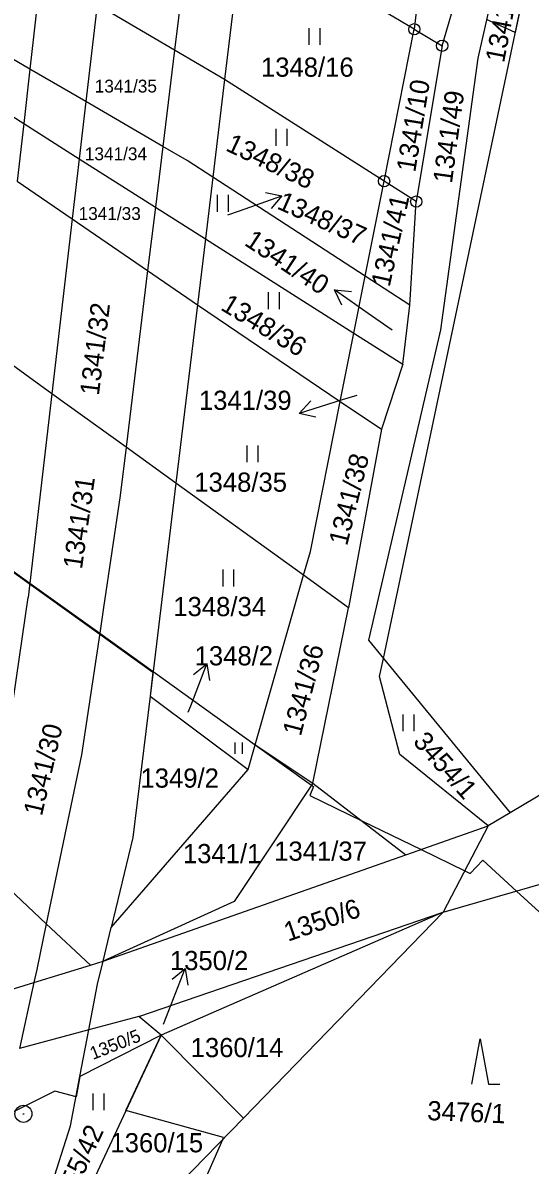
# Model space of a CAD drawing. Extents: x -735036 to -734743, y -1144813 to -1144181.
# Drawn here: x -734846.3 to -734801.3, y -1144707.5 to -1144606.3 of the extents above; entities that cross this region are included whole.
import ezdxf

# ---------------------------------------------------------------- set-up
doc = ezdxf.new("R2010")
doc.units = 0
for name, color, linetype in [('BPEJ', 7, 'Continuous'), ('Katastr_HRANICE DRÁHY', 7, 'Continuous'), ('Katastr_Hranice parcel', 7, 'Continuous'), ('Katastr_Parcelní čísla', 7, 'Continuous'), ('Katastr_Slučkované čáry', 7, 'Continuous'), ('Katastr_Značky kultur', 7, 'Continuous')]:
    doc.layers.add(name, color=color, linetype=linetype)

msp = doc.modelspace()

# ---------------------------------------------------------------- linework, layer by layer
at = {"layer": 'BPEJ'}
for points in [[(-734799.83, -1144593.94), (-734802.63, -1144607.21), (-734805.16, -1144606.06)], [(-734886.95, -1144596.85), (-734888.29, -1144609.47), (-734890, -1144625.5), (-734887.82, -1144626.59), (-734885, -1144628), (-734852.91, -1144650.88), (-734852.15, -1144651.42), (-734850.43, -1144652.65), (-734834.73, -1144663.85), (-734834.99, -1144666), (-734826.29, -1144672.48), (-734825.67, -1144670.31), (-734820.68, -1144673.87), (-734820.5, -1144674), (-734820.82, -1144674.78), (-734818.52, -1144675.9), (-734816.23, -1144677.02), (-734810.97, -1144679.57), (-734807.09, -1144681.45), (-734806.63, -1144681.68), (-734805.5, -1144680.5), (-734802.5, -1144683.25), (-734799.5, -1144686)], [(-734875.41, -1144811.46), (-734872.9, -1144805.78), (-734867.89, -1144794.43), (-734854.34, -1144763.72), (-734850.2, -1144754.32), (-734842.33, -1144736.48), (-734836.55, -1144723.38), (-734836.47, -1144723.21), (-734828.55, -1144705.26), (-734828.47, -1144705.07), (-734837.14, -1144702.69), (-734834.01, -1144696), (-734841.2, -1144699.67), (-734841.55, -1144701.48), (-734843.42, -1144700.96), (-734850.5, -1144704.5), (-734856.16, -1144706.13), (-734861.05, -1144707.56), (-734878.02, -1144712.44), (-734888.06, -1144715.34), (-734896.33, -1144716.95), (-734914.06, -1144720.39), (-734915.89, -1144720.74)]]:
    msp.add_lwpolyline(points, dxfattribs=at)
at = {"layer": 'Katastr_HRANICE DRÁHY'}
for points in [[(-734844.66, -1144601.82), (-734845.64, -1144610.44)], [(-734845.64, -1144610.44), (-734846.19, -1144615.27)], [(-734828.38, -1144611.37), (-734829.43, -1144620.02)], [(-734814.25, -1144620.37), (-734828.38, -1144611.37)], [(-734846.19, -1144615.27), (-734846.77, -1144620.37)], [(-734829.43, -1144620.02), (-734830.09, -1144625.49)], [(-734815.92, -1144628.78), (-734814.25, -1144620.37)], [(-734830.09, -1144625.49), (-734830.79, -1144631.32)], [(-734816.93, -1144633.84), (-734815.92, -1144628.78)], [(-734830.79, -1144631.32), (-734832.7, -1144647.12)], [(-734818.13, -1144639.88), (-734816.93, -1144633.84)], [(-734818.13, -1144639.88), (-734814.48, -1144642.35)], [(-734814.48, -1144642.35), (-734817.41, -1144658.17)], [(-734832.7, -1144647.12), (-734834.72, -1144663.79)], [(-734825.66, -1144670.29), (-734821.38, -1144655.27)], [(-734817.41, -1144658.17), (-734821.38, -1144655.27)], [(-734834.72, -1144663.79), (-734834.99, -1144666)], [(-734834.99, -1144666), (-734826.29, -1144672.48)], [(-734826.29, -1144672.48), (-734825.66, -1144670.29)]]:
    msp.add_lwpolyline(points, dxfattribs=at)
at = {"layer": 'Katastr_Hranice parcel'}
for points in [[(-734798.65, -1144577.31), (-734805.94, -1144609.48)], [(-734814.3, -1144662.64), (-734799.83, -1144593.94)], [(-734826.76, -1144597.94), (-734828.38, -1144611.37)], [(-734811.57, -1144606.92), (-734826.76, -1144597.94)], [(-734809.1, -1144608.38), (-734806.45, -1144599.27)], [(-734811.14, -1144603.11), (-734811.57, -1144606.92)], [(-734832.82, -1144608.77), (-734839.69, -1144604.74)], [(-734814.25, -1144620.37), (-734811.57, -1144606.92)], [(-734811.57, -1144606.92), (-734809.1, -1144608.38)], [(-734828.38, -1144611.37), (-734832.82, -1144608.77)], [(-734809.1, -1144608.38), (-734811.4, -1144622.18)], [(-734845.64, -1144610.44), (-734847.79, -1144609.19)], [(-734805.94, -1144609.48), (-734809.25, -1144633.53)], [(-734840.68, -1144613.32), (-734845.64, -1144610.44)], [(-734848.33, -1144613.91), (-734846.19, -1144615.27)], [(-734833.86, -1144617.29), (-734840.68, -1144613.32)], [(-734846.19, -1144615.27), (-734841.27, -1144618.39)], [(-734831.69, -1144618.55), (-734833.86, -1144617.29)], [(-734841.27, -1144618.39), (-734834.52, -1144622.68)], [(-734829.43, -1144620.02), (-734831.69, -1144618.55)], [(-734815.92, -1144628.78), (-734829.43, -1144620.02)], [(-734846.77, -1144620.37), (-734841.89, -1144623.71)], [(-734811.4, -1144622.18), (-734814.25, -1144620.37)], [(-734811.96, -1144631.35), (-734811.4, -1144622.18)], [(-734834.52, -1144622.68), (-734830.09, -1144625.49)], [(-734841.89, -1144623.71), (-734835.21, -1144628.29)], [(-734830.09, -1144625.49), (-734816.93, -1144633.84)], [(-734835.21, -1144628.29), (-734830.79, -1144631.32)], [(-734811.96, -1144631.35), (-734815.92, -1144628.78)], [(-734830.79, -1144631.32), (-734818.13, -1144639.88)], [(-734812.59, -1144636.59), (-734811.96, -1144631.35)], [(-734816.93, -1144633.84), (-734812.59, -1144636.59)], [(-734809.25, -1144633.53), (-734815.62, -1144661.04)], [(-734843.69, -1144639.2), (-734848.51, -1144635.73)], [(-734812.59, -1144636.59), (-734814.48, -1144642.35)], [(-734837.12, -1144643.94), (-734843.69, -1144639.2)], [(-734820.78, -1144653.18), (-734818.13, -1144639.88)], [(-734744.09, -1144641.26), (-734803.06, -1144676.31)], [(-734832.7, -1144647.12), (-734837.12, -1144643.94)], [(-734821.38, -1144655.27), (-734832.7, -1144647.12)], [(-734850.42, -1144652.54), (-734845.63, -1144655.97)], [(-734821.38, -1144655.27), (-734820.78, -1144653.18)], [(-734845.63, -1144655.97), (-734839.45, -1144660.4)], [(-734820.55, -1144673.68), (-734817.41, -1144658.17)], [(-734839.45, -1144660.4), (-734834.72, -1144663.79)], [(-734815.62, -1144661.04), (-734814.3, -1144662.64)], [(-734814.64, -1144664.24), (-734814.3, -1144662.64)], [(-734814.3, -1144662.64), (-734803.06, -1144676.31)], [(-734834.72, -1144663.79), (-734825.66, -1144670.29)], [(-734812.84, -1144671.15), (-734814.64, -1144664.24)], [(-734834.99, -1144666), (-734836.51, -1144678.49)], [(-734825.66, -1144670.29), (-734820.55, -1144673.68)], [(-734805.01, -1144677.47), (-734812.84, -1144671.15)], [(-734838.43, -1144686.49), (-734826.29, -1144672.48)], [(-734820.55, -1144673.68), (-734827.54, -1144684.16)], [(-734820.55, -1144673.68), (-734812.31, -1144680.04)], [(-734803.06, -1144676.31), (-734805.01, -1144677.47)], [(-734812.31, -1144680.04), (-734805.01, -1144677.47)], [(-734805.01, -1144677.47), (-734809.02, -1144685.13)], [(-734836.51, -1144678.49), (-734838.43, -1144686.49)], [(-734839.14, -1144689.47), (-734812.31, -1144680.04)], [(-734809.02, -1144685.13), (-734792.32, -1144680.32)], [(-734844.19, -1144686.14), (-734849.69, -1144680.98)], [(-734827.54, -1144684.16), (-734839.14, -1144689.47)], [(-734835.97, -1144694.36), (-734809.02, -1144685.13)], [(-734809.02, -1144685.13), (-734834.01, -1144696)], [(-734826.71, -1144703.36), (-734809.02, -1144685.13)], [(-734840.27, -1144689.82), (-734844.19, -1144686.14)], [(-734839.14, -1144689.47), (-734838.43, -1144686.49)], [(-734845.28, -1144691.36), (-734840.27, -1144689.82)], [(-734840.27, -1144689.82), (-734839.14, -1144689.47)], [(-734839.64, -1144691.51), (-734839.14, -1144689.47)], [(-734852.46, -1144693.56), (-734845.28, -1144691.36)], [(-734840.41, -1144695.55), (-734839.64, -1144691.51)], [(-734835.97, -1144694.36), (-734840.41, -1144695.55)], [(-734834.01, -1144696), (-734835.97, -1144694.36)], [(-734840.41, -1144695.55), (-734846.56, -1144697.19)], [(-734834.01, -1144696), (-734843.82, -1144716.99)], [(-734841.2, -1144699.67), (-734840.41, -1144695.55)], [(-734834.01, -1144696), (-734841.2, -1144699.67)], [(-734834.01, -1144696), (-734826.71, -1144703.36)], [(-734842.04, -1144704.04), (-734841.2, -1144699.67)], [(-734845.64, -1144715.39), (-734842.04, -1144704.04)], [(-734832.35, -1144709.16), (-734826.71, -1144703.36)]]:
    msp.add_lwpolyline(points, dxfattribs=at)
at = {"layer": 'Katastr_Parcelní čísla'}
for p, q in [((-734824.77, -1144621.39), (-734823.3, -1144621.66)), ((-734828.1, -1144623.35), (-734827.07, -1144622.99)), ((-734817.99, -1144631.36), (-734818.63, -1144630)), ((-734813.52, -1144633.57), (-734815.35, -1144632.29)), ((-734816.67, -1144639.35), (-734817.95, -1144639.75)), ((-734820.3, -1144641.27), (-734821.77, -1144640.94)), ((-734831.13, -1144664.06), (-734829.97, -1144663.11)), ((-734831.6, -1144667.41), (-734831.39, -1144666.85)), ((-734833.04, -1144691.04), (-734831.87, -1144690.11)), ((-734833.8, -1144695.04), (-734833.33, -1144693.83))]:
    msp.add_line(p, q, dxfattribs=at)
for points in [[(-734827.07, -1144622.99), (-734823.3, -1144621.66), (-734824.27, -1144622.8)], [(-734815.35, -1144632.29), (-734818.63, -1144630), (-734817.13, -1144630.13)], [(-734817.95, -1144639.75), (-734821.77, -1144640.94), (-734820.75, -1144639.84)], [(-734831.39, -1144666.85), (-734829.97, -1144663.11), (-734829.73, -1144664.59)], [(-734833.33, -1144693.83), (-734831.87, -1144690.11), (-734831.65, -1144691.59)]]:
    msp.add_lwpolyline(points, dxfattribs=at)
at = {"layer": 'Katastr_Slučkované čáry'}
for points in [[(-734831.41, -1144597.28), (-734832.82, -1144608.77)], [(-734839.69, -1144604.74), (-734840.68, -1144613.32)], [(-734832.82, -1144608.77), (-734833.86, -1144617.29)], [(-734840.68, -1144613.32), (-734841.27, -1144618.39)], [(-734833.86, -1144617.29), (-734834.52, -1144622.68)], [(-734841.27, -1144618.39), (-734841.89, -1144623.71)], [(-734834.52, -1144622.68), (-734835.21, -1144628.29)], [(-734841.89, -1144623.71), (-734843.69, -1144639.2)], [(-734835.21, -1144628.29), (-734837.12, -1144643.94)], [(-734843.69, -1144639.2), (-734845.63, -1144655.97)], [(-734837.12, -1144643.94), (-734837.64, -1144648.22)], [(-734837.64, -1144648.22), (-734839.11, -1144658.14)], [(-734845.63, -1144655.97), (-734845.78, -1144657.26)], [(-734848.46, -1144675.36), (-734845.78, -1144657.26)], [(-734839.11, -1144658.14), (-734839.45, -1144660.4)], [(-734839.45, -1144660.4), (-734841.08, -1144671.17)], [(-734841.08, -1144671.17), (-734844.19, -1144686.14)], [(-734844.19, -1144686.14), (-734845.03, -1144690.2)], [(-734845.03, -1144690.2), (-734845.28, -1144691.36)], [(-734845.28, -1144691.36), (-734846.56, -1144697.19)]]:
    msp.add_lwpolyline(points, dxfattribs=at)
at = {"layer": 'Katastr_Značky kultur'}
for p, q in [((-734820.92, -1144606.81), (-734820.92, -1144608.31)), ((-734819.92, -1144608.31), (-734819.92, -1144606.81)), ((-734811.62, -1144606.92), (-734811.52, -1144606.92)), ((-734809.15, -1144608.38), (-734809.05, -1144608.38)), ((-734823.84, -1144615.74), (-734823.84, -1144617.24)), ((-734822.84, -1144617.24), (-734822.84, -1144615.74)), ((-734814.3, -1144620.37), (-734814.2, -1144620.37)), ((-734829.05, -1144621.59), (-734829.05, -1144623.09)), ((-734828.05, -1144623.09), (-734828.05, -1144621.59)), ((-734811.45, -1144622.18), (-734811.35, -1144622.18)), ((-734824.51, -1144630.2), (-734824.51, -1144631.7)), ((-734823.51, -1144631.7), (-734823.51, -1144630.2)), ((-734826.41, -1144643.77), (-734826.41, -1144645.27)), ((-734825.41, -1144645.27), (-734825.41, -1144643.77)), ((-734828.55, -1144654.77), (-734828.55, -1144656.27)), ((-734827.55, -1144656.27), (-734827.55, -1144654.77)), ((-734812.58, -1144667.6), (-734812.58, -1144669.1)), ((-734811.58, -1144669.1), (-734811.58, -1144667.6)), ((-734827.47, -1144670.09), (-734827.47, -1144671.09)), ((-734826.81, -1144671.09), (-734826.81, -1144670.09)), ((-734840.05, -1144701.17), (-734840.05, -1144702.67)), ((-734839.05, -1144702.67), (-734839.05, -1144701.17)), ((-734846.26, -1144702.98), (-734846.16, -1144702.98))]:
    msp.add_line(p, q, dxfattribs=at)
msp.add_lwpolyline([(-734806.48, -1144700.34), (-734805.73, -1144696.34), (-734804.98, -1144700.34), (-734803.98, -1144700.34)], dxfattribs=at)
for centre, radius in [((-734811.57, -1144606.92), 0.499), ((-734809.1, -1144608.38), 0.499), ((-734814.25, -1144620.37), 0.499), ((-734811.4, -1144622.18), 0.499), ((-734846.21, -1144702.98), 0.756)]:
    msp.add_circle(centre, radius, dxfattribs=at)

# ---------------------------------------------------------------- texts
at = {"layer": 'Katastr_Parcelní čísla'}
for s, height, rotation, p in [('1341/50', 1.7, 79.1371, (-734803.62, -1144609.95)), ('1341/10', 1.7, 80.8033, (-734811.49, -1144619.64)), ('1341/49', 1.7, 82.2448, (-734808.24, -1144620.62)), ('1348/38', 1.7, 334.718, (-734828.38, -1144617.62)), ('1348/37', 1.7, 335.921, (-734823.83, -1144622.77)), ('1341/41', 1.7, 77.5667, (-734813.76, -1144629.81)), ('1341/40', 1.7, 326.5752, (-734826.72, -1144625.98)), ('1341/32', 1.7, 82.9954, (-734839.53, -1144639.41)), ('1348/36', 1.7, 328.6787, (-734828.83, -1144631.71)), ('1341/38', 1.7, 76.1334, (-734817.53, -1144652.73)), ('1341/31', 1.7, 81.8408, (-734841.03, -1144654.79)), ('1341/36', 1.7, 75.4378, (-734821.63, -1144669.6)), ('1341/30', 1.7, 76.934, (-734844.58, -1144676.67)), ('3454/1', 1.7, 311.6778, (-734811.76, -1144670.07)), ('1350/6', 1.7, 18.9765, (-734822.77, -1144687.74)), ('1350/5', 1.14, 21.41, (-734840.05, -1144698.21)), ('3476/1', 1.7, 357.5604, (-734810.45, -1144703.53)), ('1355/42', 1.7, 65.118, (-734842.51, -1144711.93))]:
    msp.add_text(s, height=height, rotation=rotation, dxfattribs=at).set_placement(p)
for s, height, p in [('1348/16', 1.7, (-734825.16, -1144611.12)), ('1341/35', 1.14, (-734839.89, -1144612.52)), ('1341/34', 1.14, (-734840.77, -1144618.52)), ('1341/33', 1.14, (-734841.32, -1144623.81)), ('1341/39', 1.7, (-734830.66, -1144640.63)), ('1348/35', 1.7, (-734831.07, -1144647.88)), ('1348/34', 1.7, (-734832.93, -1144658.9)), ('1348/2', 1.7, (-734831.04, -1144663.26)), ('1349/2', 1.7, (-734835.84, -1144674.09)), ('1341/37', 1.7, (-734823.99, -1144680.56)), ('1341/1', 1.7, (-734832.08, -1144680.78)), ('1350/2', 1.7, (-734833.23, -1144690.25)), ('1360/14', 1.7, (-734831.39, -1144697.96)), ('1360/15', 1.7, (-734838.5, -1144706.39))]:
    msp.add_text(s, height=height, dxfattribs=at).set_placement(p)

doc.saveas('drawing.dxf')
